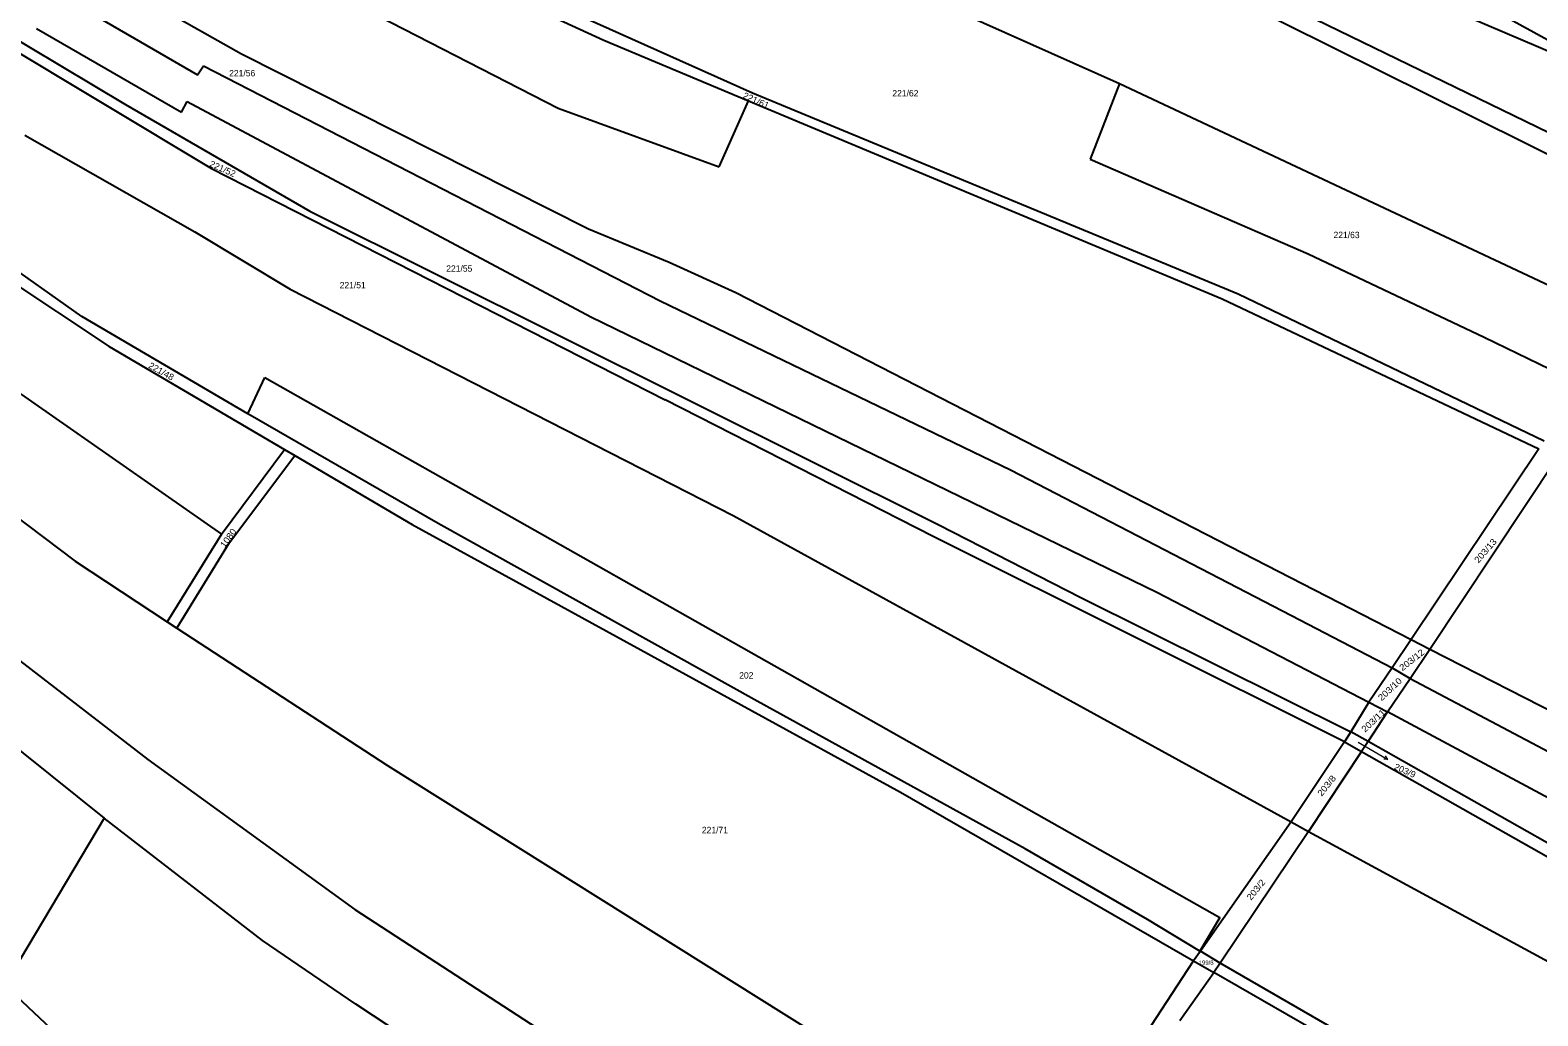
# Model space of a CAD drawing. Extents: x -694609 to -690140, y -1033292 to -1029794.
# Drawn here: x -693359.6 to -692957.6, y -1031078.6 to -1030815.9 of the extents above; entities that cross this region are included whole.
import ezdxf
from ezdxf.enums import TextEntityAlignment as Align

# ---------------------------------------------------------------- set-up
doc = ezdxf.new("R2010")
doc.units = 0
doc.header["$LTSCALE"] = 0.68
doc.layers.add('1', color=7, linetype='Continuous', lineweight=25)
doc.layers.add('7', color=7, linetype='Continuous', lineweight=13)
doc.layers.add('2', color=7, linetype='Continuous')

msp = doc.modelspace()

# ---------------------------------------------------------------- linework, layer by layer
at = {"layer": '1'}
for p, q in [((-693412.42, -1030770.87), (-693314.98, -1030827.81)), ((-693393.57, -1030771.21), (-693303.2, -1030822.15)), ((-693430.47, -1030778.14), (-693334.12, -1030835.68)), ((-693422.54, -1030785.84), (-693311.23, -1030852.77)), ((-693265.54, -1030788.41), (-693167.03, -1030832.57)), ((-693266.25, -1030791.09), (-693206.66, -1030818.52)), ((-692931.9, -1030831.23), (-693003.31, -1030791.93)), ((-693300.88, -1030794.51), (-693218.77, -1030836.67)), ((-693018.11, -1030794.43), (-692931.9, -1030831.23)), ((-693117.78, -1030808.41), (-693069.12, -1030830.06)), ((-692917.1, -1030867.85), (-693037.79, -1030807.89)), ((-692916.05, -1030862.05), (-693020.03, -1030811.51)), ((-693357.89, -1030815.44), (-693319.26, -1030837.7)), ((-693206.66, -1030818.52), (-693168.11, -1030834.67)), ((-693345.78, -1030892.23), (-693440.57, -1030824.99)), ((-693303.2, -1030822.15), (-693210.69, -1030868.87)), ((-693314.98, -1030827.81), (-693313.37, -1030825.41)), ((-693167.03, -1030832.57), (-693037.51, -1030886.17)), ((-693069.12, -1030830.06), (-693077, -1030850.22)), ((-693069.12, -1030830.06), (-692934.37, -1030893.4)), ((-693334.12, -1030835.68), (-693285.04, -1030864.09)), ((-693319.26, -1030837.7), (-693317.67, -1030834.92)), ((-693317.67, -1030834.92), (-693210.14, -1030892.28)), ((-693218.77, -1030836.67), (-693175.89, -1030852.33)), ((-693175.89, -1030852.33), (-693168.11, -1030834.67)), ((-693168.11, -1030834.67), (-693041.81, -1030887.47)), ((-693361.02, -1030843.9), (-693315.67, -1030869.63)), ((-693311.23, -1030852.77), (-693190.26, -1030914.42)), ((-693077, -1030850.22), (-693018.84, -1030875.48)), ((-693285.04, -1030864.09), (-693117.3, -1030947.77)), ((-693424.96, -1030868.97), (-693308.58, -1030950.27)), ((-693210.69, -1030868.87), (-693189.21, -1030877.72)), ((-693315.67, -1030869.63), (-693290.29, -1030884.95)), ((-693018.84, -1030875.48), (-692971.97, -1030897.72)), ((-693189.21, -1030877.72), (-693171.41, -1030885.84)), ((-693366.31, -1030881.73), (-693338.53, -1030900.17)), ((-693290.29, -1030884.95), (-693172.17, -1030945.27)), ((-693171.41, -1030885.84), (-692991.38, -1030978.3)), ((-693041.81, -1030887.47), (-692957.41, -1030927.47)), ((-693037.51, -1030886.17), (-692955.99, -1030925.37)), ((-693301.57, -1030918.14), (-693345.78, -1030892.23)), ((-693210.14, -1030892.28), (-693059.2, -1030965.73)), ((-693426.71, -1030897.7), (-693347.54, -1030957.43)), ((-693338.53, -1030900.17), (-693291.8, -1030927.62)), ((-692971.97, -1030897.72), (-692945.85, -1030910.38)), ((-693301.57, -1030918.14), (-693296.97, -1030908.44)), ((-693296.97, -1030908.44), (-693042.37, -1031052.42)), ((-693118.85, -1030950.85), (-693190.26, -1030914.42)), ((-693250.84, -1030947.42), (-693301.57, -1030918.14)), ((-693308.58, -1030950.27), (-693291.8, -1030927.62)), ((-693306.46, -1030952.47), (-693289.01, -1030929.26)), ((-693291.8, -1030927.62), (-693289.01, -1030929.26)), ((-693289.01, -1030929.26), (-693257.69, -1030947.66)), ((-692957.41, -1030927.47), (-692991.38, -1030978.3)), ((-693098.23, -1030933.07), (-693023.31, -1030971.96)), ((-692986.42, -1030980.85), (-692952.63, -1030930.07)), ((-693172.17, -1030945.27), (-693023.39, -1031026.96)), ((-693257.69, -1030947.66), (-693127.54, -1031019.02)), ((-693165.72, -1030994.79), (-693250.84, -1030947.42)), ((-693117.3, -1030947.77), (-693079.48, -1030967.12)), ((-693404.1, -1030951.76), (-693328.16, -1031010.33)), ((-693308.58, -1030950.27), (-693323.01, -1030973.6)), ((-693320.47, -1030975.28), (-693306.46, -1030952.47)), ((-693009.22, -1031005.6), (-693118.85, -1030950.85)), ((-693428.04, -1030955.2), (-693339.81, -1031025.97)), ((-693347.54, -1030957.43), (-693323.01, -1030973.6)), ((-693059.2, -1030965.73), (-693002.65, -1030995.03)), ((-693079.48, -1030967.12), (-693007.45, -1031002.92)), ((-693323.01, -1030973.6), (-693320.47, -1030975.28)), ((-693023.31, -1030971.96), (-692996.47, -1030985.91)), ((-693320.47, -1030975.28), (-693264.29, -1031011.93)), ((-692991.38, -1030978.3), (-692996.47, -1030985.91)), ((-692991.63, -1030988.68), (-692986.42, -1030980.85)), ((-692991.38, -1030978.3), (-692986.42, -1030980.85)), ((-692986.42, -1030980.85), (-692917.02, -1031016.49)), ((-692996.47, -1030985.91), (-693002.65, -1030995.03)), ((-692997.76, -1030997.63), (-692991.63, -1030988.68)), ((-692996.47, -1030985.91), (-692991.63, -1030988.68)), ((-692991.63, -1030988.68), (-692925.86, -1031023.52)), ((-693094.27, -1031034.08), (-693165.72, -1030994.79)), ((-693002.65, -1030995.03), (-693007.45, -1031002.92)), ((-693002.85, -1031005.53), (-692997.76, -1030997.63)), ((-693002.65, -1030995.03), (-692997.76, -1030997.63)), ((-692872.91, -1031064.37), (-692997.76, -1030997.63)), ((-693009.22, -1031005.6), (-693023.39, -1031026.96)), ((-693007.45, -1031002.92), (-693009.22, -1031005.6)), ((-693009.22, -1031005.6), (-693004.63, -1031008.2)), ((-693002.85, -1031005.53), (-693007.45, -1031002.92)), ((-693002.85, -1031005.53), (-693004.63, -1031008.2)), ((-692951.06, -1031034.81), (-693002.85, -1031005.53)), ((-693004.63, -1031008.2), (-693018.79, -1031029.47)), ((-693004.63, -1031008.2), (-692952.63, -1031037.6)), ((-693328.16, -1031010.33), (-693273.03, -1031050.26)), ((-693127.54, -1031019.02), (-693049.43, -1031064)), ((-693339.81, -1031025.97), (-693366.29, -1031070.45)), ((-693297.62, -1031058.59), (-693339.81, -1031025.97)), ((-693023.39, -1031026.96), (-693047.61, -1031061.42)), ((-693018.79, -1031029.47), (-693042.29, -1031064.64)), ((-693023.39, -1031026.96), (-693018.79, -1031029.47)), ((-693018.79, -1031029.47), (-692930.66, -1031077.38)), ((-693061.72, -1031052.94), (-693094.27, -1031034.08)), ((-693273.03, -1031050.26), (-693153.72, -1031127.85)), ((-693047.71, -1031061.36), (-693061.72, -1031052.94)), ((-693042.37, -1031052.42), (-693047.71, -1031061.36)), ((-693272.71, -1031075.54), (-693297.62, -1031058.59)), ((-693047.61, -1031061.42), (-693049.43, -1031064)), ((-693047.61, -1031061.42), (-693047.71, -1031061.36)), ((-693042.29, -1031064.64), (-693047.61, -1031061.42)), ((-693087.76, -1031122.58), (-693049.43, -1031064)), ((-693049.43, -1031064), (-693044.03, -1031067.11)), ((-693042.29, -1031064.64), (-693044.03, -1031067.11)), ((-693005.7, -1031085.79), (-693042.29, -1031064.64)), ((-693053.05, -1031079.91), (-693044.03, -1031067.11)), ((-693018.06, -1031082.02), (-693044.03, -1031067.11)), ((-693366.29, -1031070.45), (-693335.04, -1031099.87)), ((-693195.97, -1031126.12), (-693272.71, -1031075.54))]:
    msp.add_line(p, q, dxfattribs=at)
for points in [[(-693313.37, -1030825.41), (-693191.62, -1030888.01), (-693098.23, -1030933.07)], [(-693264.29, -1031011.93), (-693087.76, -1031122.58), (-693082.21, -1031125.35)]]:
    msp.add_lwpolyline(points, dxfattribs=at)
at = {"layer": '7'}
msp.add_line((-692997.601, -1031010.29), (-692998.218, -1031009.356), dxfattribs=at)
msp.add_lwpolyline([(-693005.5, -1031005.69), (-693000.2, -1031008.79), (-692997.601, -1031010.29), (-692998.719, -1031010.223)], dxfattribs=at)

# ---------------------------------------------------------------- texts
at = {"layer": '2'}
for s, height, p in [('221/56', 1.7, (-693303.04, -1030828.185)), ('221/62', 1.7, (-693126.24, -1030833.545)), ('221/63', 1.7, (-693008.63, -1030871.315)), ('221/55', 1.7, (-693245.17, -1030880.265)), ('221/51', 1.7, (-693273.58, -1030884.695)), ('202', 1.7, (-693168.649, -1030988.725)), ('221/71', 1.7, (-693177.02, -1031029.955)), ('199/8', 1.14, (-693046.059, -1031065.035))]:
    msp.add_text(s, height=height, dxfattribs=at).set_placement(p, align=Align.CENTER)
for s, rotation, width, p in [('221/61', 336, 1.05, (-693166.3862, -1030835.3763)), ('221/52', 336, 1.05, (-693308.5962, -1030853.6163)), ('221/48', 331, 1.05, (-693325.0151, -1030907.568)), ('1080', 54, 1.1, (-693306.081, -1030951.7746)), ('203/13', 49, 1.1, (-692970.9622, -1030955.2141)), ('203/12', 38, 1.1, (-692990.7213, -1030984.4369)), ('203/10', 43, 1.1, (-692996.4847, -1030992.1847)), ('203/11', 43, 1.1, (-693000.9047, -1031000.5747)), ('203/9', 336, 1.05, (-692993.3957, -1031014.0561)), ('203/8', 51, 1.1, (-693013.2785, -1031017.8144)), ('203/2', 51, 1.1, (-693032.1185, -1031045.5444))]:
    msp.add_text(s, height=1.7, rotation=rotation, dxfattribs=dict(at, width=width)).set_placement(p, align=Align.CENTER)

doc.saveas('drawing.dxf')
